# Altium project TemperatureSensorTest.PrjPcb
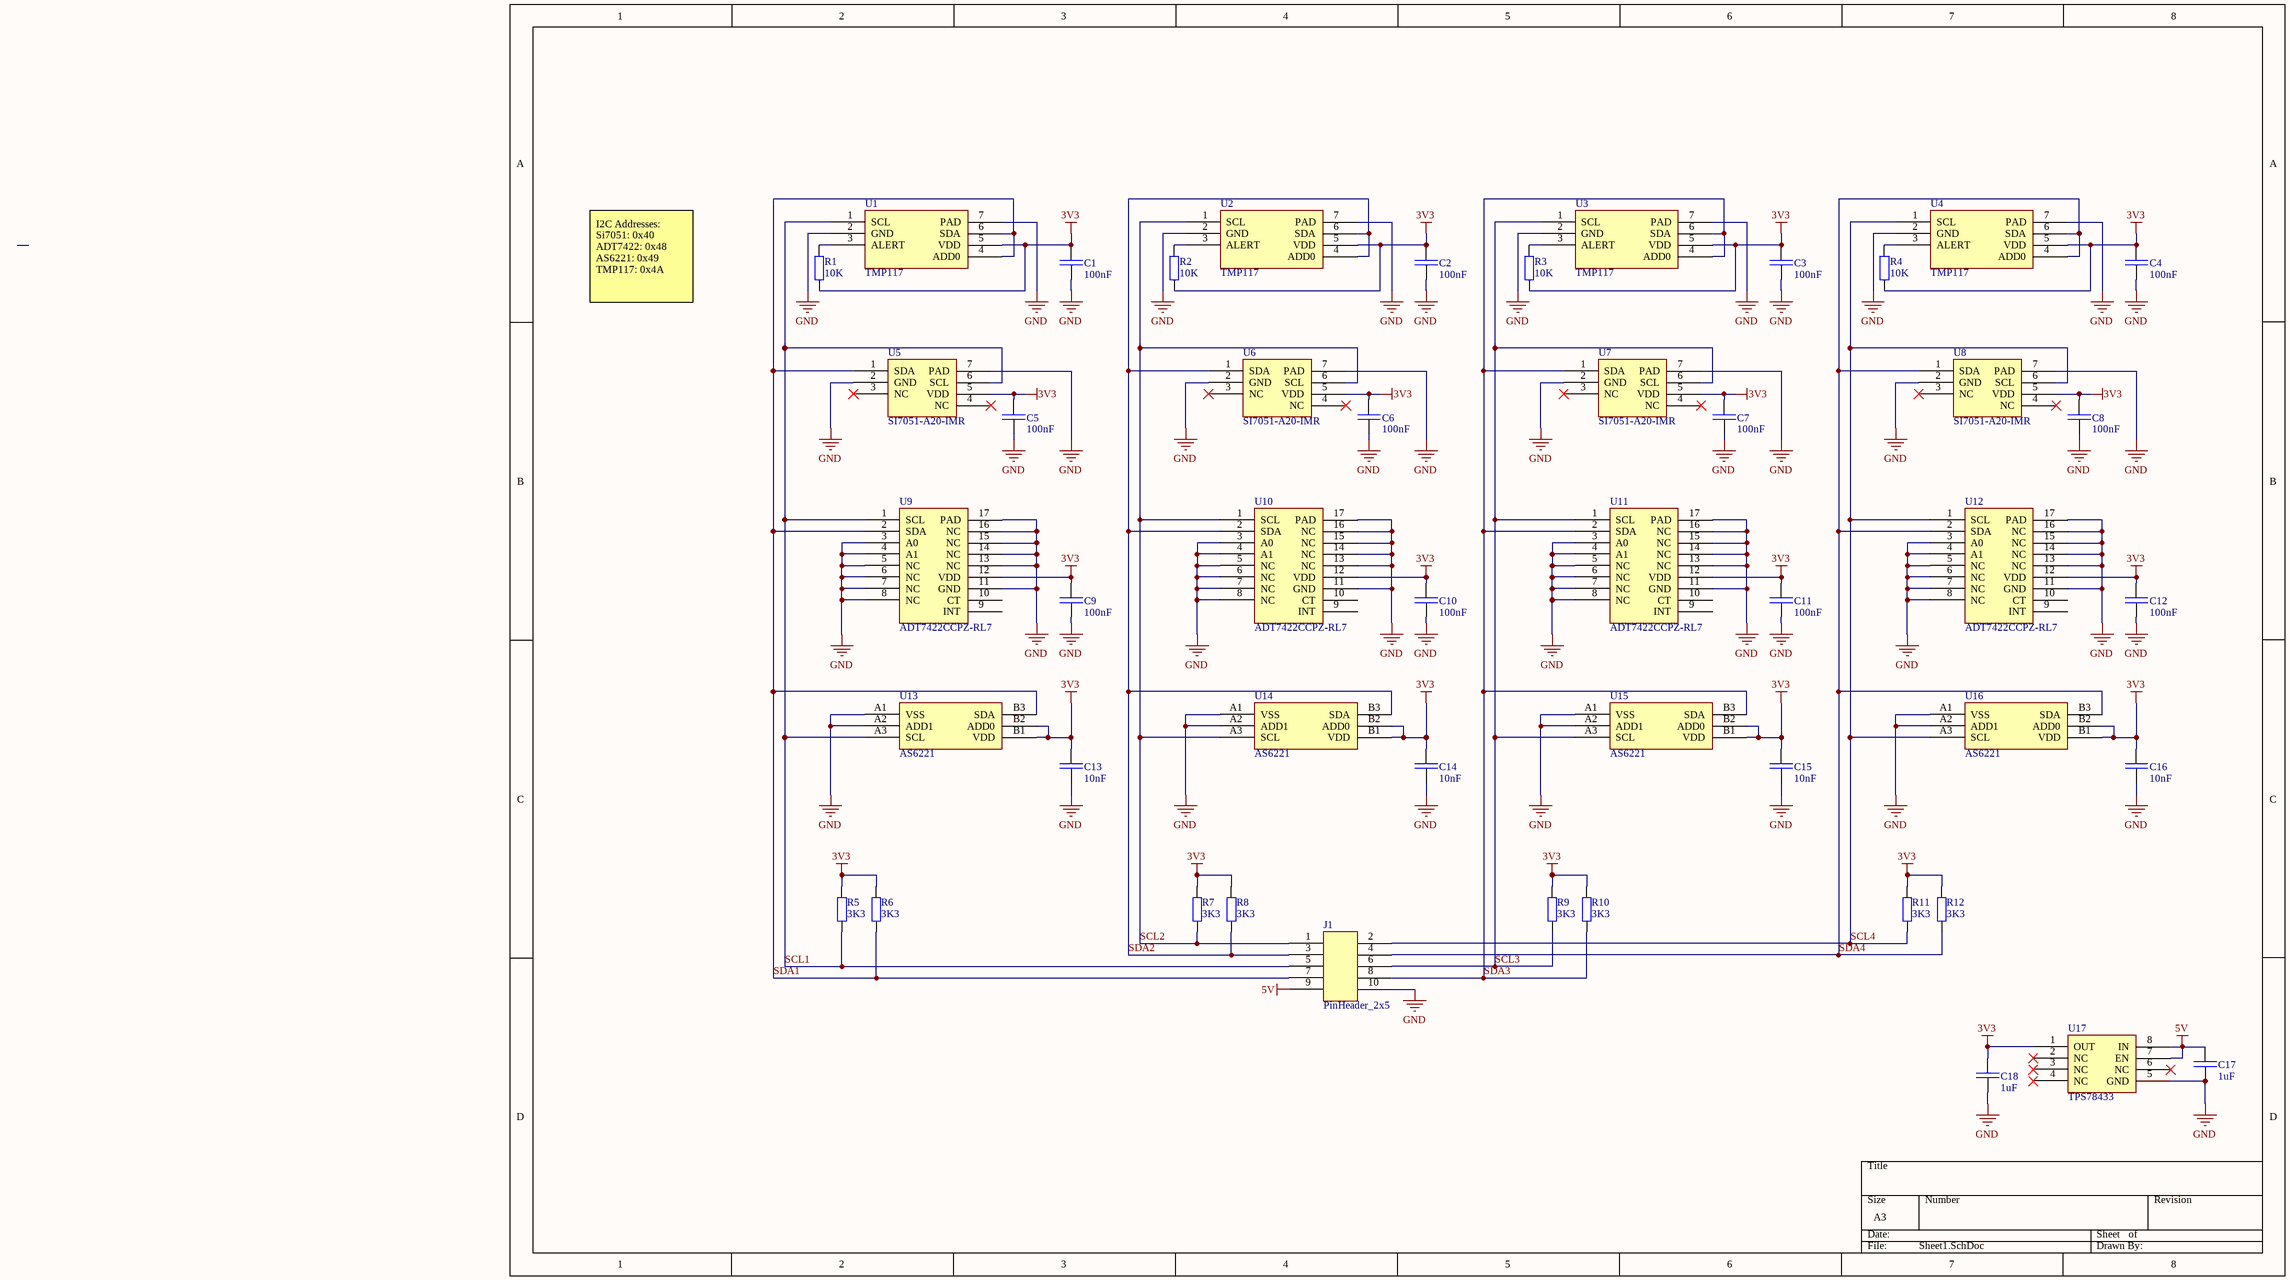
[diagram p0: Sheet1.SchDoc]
1 sheet, 48 parts. Net scope: global (net labels, ports and power ports of the same name join across sheets).
Board file: PCB1.PcbDoc

## Sheet Sheet1.SchDoc
size A3; SheetNumber: 1; SheetTotal: 1

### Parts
C1  100nF  [CAP_SM0603_YAGEOCC2_N]
C2  100nF  [CAP_SM0603_YAGEOCC2_N]
C3  100nF  [CAP_SM0603_YAGEOCC2_N]
C4  100nF  [CAP_SM0603_YAGEOCC2_N]
C5  100nF  [CAP_SM0603_YAGEOCC2_N]
C6  100nF  [CAP_SM0603_YAGEOCC2_N]
C7  100nF  [CAP_SM0603_YAGEOCC2_N]
C8  100nF  [CAP_SM0603_YAGEOCC2_N]
C9  100nF  [CAP_SM0603_YAGEOCC2_N]
C10  100nF  [CAP_SM0603_YAGEOCC2_N]
C11  100nF  [CAP_SM0603_YAGEOCC2_N]
C12  100nF  [CAP_SM0603_YAGEOCC2_N]
C13  10nF  [CAP_SM0402_YAGEOCC2_N]
C14  10nF  [CAP_SM0402_YAGEOCC2_N]
C15  10nF  [CAP_SM0402_YAGEOCC2_N]
C16  10nF  [CAP_SM0402_YAGEOCC2_N]
C17  1uF  [CAP_SM0805_YAGEOCC2_N]
C18  1uF  [CAP_SM0805_YAGEOCC2_N]
J1  PinHeader_2x5  [PinHeader_2x5_2.54mm]
R1  10K  [RES_SM0603_YAGEORC_N]
R2  10K  [RES_SM0603_YAGEORC_N]
R3  10K  [RES_SM0603_YAGEORC_N]
R4  10K  [RES_SM0603_YAGEORC_N]
R5  3K3  [RES_SM0603_YAGEORC_N]
R6  3K3  [RES_SM0603_YAGEORC_N]
R7  3K3  [RES_SM0603_YAGEORC_N]
R8  3K3  [RES_SM0603_YAGEORC_N]
R9  3K3  [RES_SM0603_YAGEORC_N]
R10  3K3  [RES_SM0603_YAGEORC_N]
R11  3K3  [RES_SM0603_YAGEORC_N]
R12  3K3  [RES_SM0603_YAGEORC_N]
U1  TMP117  [TMP117(N/M)AIDRV_WSON]
U2  TMP117  [TMP117(N/M)AIDRV_WSON]
U3  TMP117  [TMP117(N/M)AIDRV_WSON]
U4  TMP117  [TMP117(N/M)AIDRV_WSON]
U5  SI7051-A20-IMR  [SI7050/1/2/3/4/5]
U6  SI7051-A20-IMR  [SI7050/1/2/3/4/5]
U7  SI7051-A20-IMR  [SI7050/1/2/3/4/5]
U8  SI7051-A20-IMR  [SI7050/1/2/3/4/5]
U9  ADT7422CCPZ-RL7  [ADT7422_QFN]
U10  ADT7422CCPZ-RL7  [ADT7422_QFN]
U11  ADT7422CCPZ-RL7  [ADT7422_QFN]
U12  ADT7422CCPZ-RL7  [ADT7422_QFN]
U13  AS6221  [AS6221_BGA]
U14  AS6221  [AS6221_BGA]
U15  AS6221  [AS6221_BGA]
U16  AS6221  [AS6221_BGA]
U17  TPS78433  [TPS784xxxQDRBRQ1_SON]

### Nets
3V3: C1.2 C2.2 C3.2 C4.2 C5.2 C6.2 C7.2 C8.2 C9.2 C10.2 C11.2 C12.2 C13.1 C14.1 C15.1 C16.1 C18.2 R1.1 R2.1 R3.1 R4.1 R5.2 R6.2 R7.2 R8.2 R9.2 R10.2 R11.2 R12.2 U1.5(VDD) U2.5(VDD) U3.5(VDD) U4.5(VDD) U5.5(VDD) U6.5(VDD) U7.5(VDD) U8.5(VDD) U9.12(VDD) U10.12(VDD) U11.12(VDD) U12.12(VDD) U13.B1(VDD) U13.B2(ADD0) U14.B1(VDD) U14.B2(ADD0) U15.B1(VDD) U15.B2(ADD0) U16.B1(VDD) U16.B2(ADD0) U17.1(OUT)
5V: C17.2 J1.9 U17.7(EN) U17.8(IN)
GND: C1.1 C2.1 C3.1 C4.1 C5.1 C6.1 C7.1 C8.1 C9.1 C10.1 C11.1 C12.1 C13.2 C14.2 C15.2 C16.2 C17.1 C18.1 J1.10 U1.2(GND) U1.7(PAD) U2.2(GND) U2.7(PAD) U3.2(GND) U3.7(PAD) U4.2(GND) U4.7(PAD) U5.2(GND) U5.7(PAD) U6.2(GND) U6.7(PAD) U7.2(GND) U7.7(PAD) U8.2(GND) U8.7(PAD) U9.3(A0) U9.4(A1) U9.5(NC) U9.6(NC) U9.7(NC) U9.8(NC) U9.11(GND) U9.13(NC) U9.14(NC) U9.15(NC) U9.16(NC) U9.17(PAD) U10.3(A0) U10.4(A1) U10.5(NC) U10.6(NC) U10.7(NC) U10.8(NC) U10.11(GND) U10.13(NC) U10.14(NC) U10.15(NC) U10.16(NC) U10.17(PAD) U11.3(A0) U11.4(A1) U11.5(NC) U11.6(NC) U11.7(NC) U11.8(NC) U11.11(GND) U11.13(NC) U11.14(NC) U11.15(NC) U11.16(NC) U11.17(PAD) U12.3(A0) U12.4(A1) U12.5(NC) U12.6(NC) U12.7(NC) U12.8(NC) U12.11(GND) U12.13(NC) U12.14(NC) U12.15(NC) U12.16(NC) U12.17(PAD) U13.A1(VSS) U13.A2(ADD1) U14.A1(VSS) U14.A2(ADD1) U15.A1(VSS) U15.A2(ADD1) U16.A1(VSS) U16.A2(ADD1) U17.5(GND)
SCL1: J1.5 R5.1 U1.1(SCL) U5.6(SCL) U9.1(SCL) U13.A3(SCL)
SCL2: J1.1 R7.1 U2.1(SCL) U6.6(SCL) U10.1(SCL) U14.A3(SCL)
SCL3: J1.6 R9.1 U3.1(SCL) U7.6(SCL) U11.1(SCL) U15.A3(SCL)
SCL4: J1.2 R11.1 U4.1(SCL) U8.6(SCL) U12.1(SCL) U16.A3(SCL)
SDA1: J1.7 R6.1 U1.4(ADD0) U1.6(SDA) U5.1(SDA) U9.2(SDA) U13.B3(SDA)
SDA2: J1.3 R8.1 U2.4(ADD0) U2.6(SDA) U6.1(SDA) U10.2(SDA) U14.B3(SDA)
SDA3: J1.8 R10.1 U3.4(ADD0) U3.6(SDA) U7.1(SDA) U11.2(SDA) U15.B3(SDA)
SDA4: J1.4 R12.1 U4.4(ADD0) U4.6(SDA) U8.1(SDA) U12.2(SDA) U16.B3(SDA)
NetR1_2: R1.2 U1.3(ALERT)
NetR2_2: R2.2 U2.3(ALERT)
NetR3_2: R3.2 U3.3(ALERT)
NetR4_2: R4.2 U4.3(ALERT)

Not connected (* = marked no-connect by the designer): U5 3(NC)* 4(NC)*; U6 3(NC)* 4(NC)*; U7 3(NC)* 4(NC)*; U8 3(NC)* 4(NC)*; U9 9(INT) 10(CT); U10 9(INT) 10(CT); U11 9(INT) 10(CT); U12 9(INT) 10(CT); U17 2(NC)* 3(NC)* 4(NC)* 6(NC)*

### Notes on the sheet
- I2C Addresses:
  Si7051: 0x40
  ADT7422: 0x48
  AS6221: 0x49
  TMP117: 0x4A

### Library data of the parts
C1-C12 = CC0603KRX7R9BB104: CAP 100nF SM0603 X7R 50V YAGEO CC2; Tolerance (%): 10; Voltage Rating (Volts): 50
C13-C16 = CC0402KRX7R9BB103: CAP 10nF SM0402 X7R 50V YAGEO CC2; Manufacturer Part Number: CC0603KRX7R9BB103; Tolerance (%): 10; Voltage Rating (Volts): 50
C17 C18 = CC0805KKX7R8BB105: CAP 1uF SM0805 X7R 25V YAGEO CC2; Tolerance (%): 10; Voltage Rating (Volts): 25
J1 = PinHeader_2x5_2.54mm: PinHeader_2x5 2.54mm Pitch
R1-R4 = RC0603FR-0710KL: RES 10K SM0603 YAGEO RC_L; Power (Watts): 0.1; Resistance (Ohms): 10000; Tolerance (%): 1
R5-R12 = RC0603FR-073K3L: RES 3.3K SM0603 YAGEO RC_L; Manufacturer Part Number: RC0603FR-0710KL; Power (Watts): 0.1; Resistance (Ohms): 10000; Tolerance (%): 1
U1-U4 = TMP117NAIDRVR: TMP117 High-Accuracy, Low-Power, Digital Temperature Sensor, -55°C bis 150°C, 16b 6-WSON (2x2)
U5-U8 = SI7051-A20-IMR: Si7051-A20 Temperature Sensor ±0.1°C maximum accuracy, Digital I2C, -40°C ~ 125°C 14b 6-DFN (3x3)
U9-U12 = ADT7422CCPZ-RL7: ADT7422 Temperature Sensor, ±0.1°C Accuracy, 16b, Digital I2C / -40°C bis 125°C 16-LFCSP-WQ (4x4)
U13-U16 = AS6221-AWLT-S: AS6221 Temperature Sensor Digital -40°C ~ 125°C 16b 6-WLCSP (1.5x1.03)
U17 = TPS78433QWDRBRQ1: TPS78433-Q1 3.3V, 300-mA, High-PSRR Low-Dropout Voltage Regulator With High Accuracy and Enable,  8-SON (3x3)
